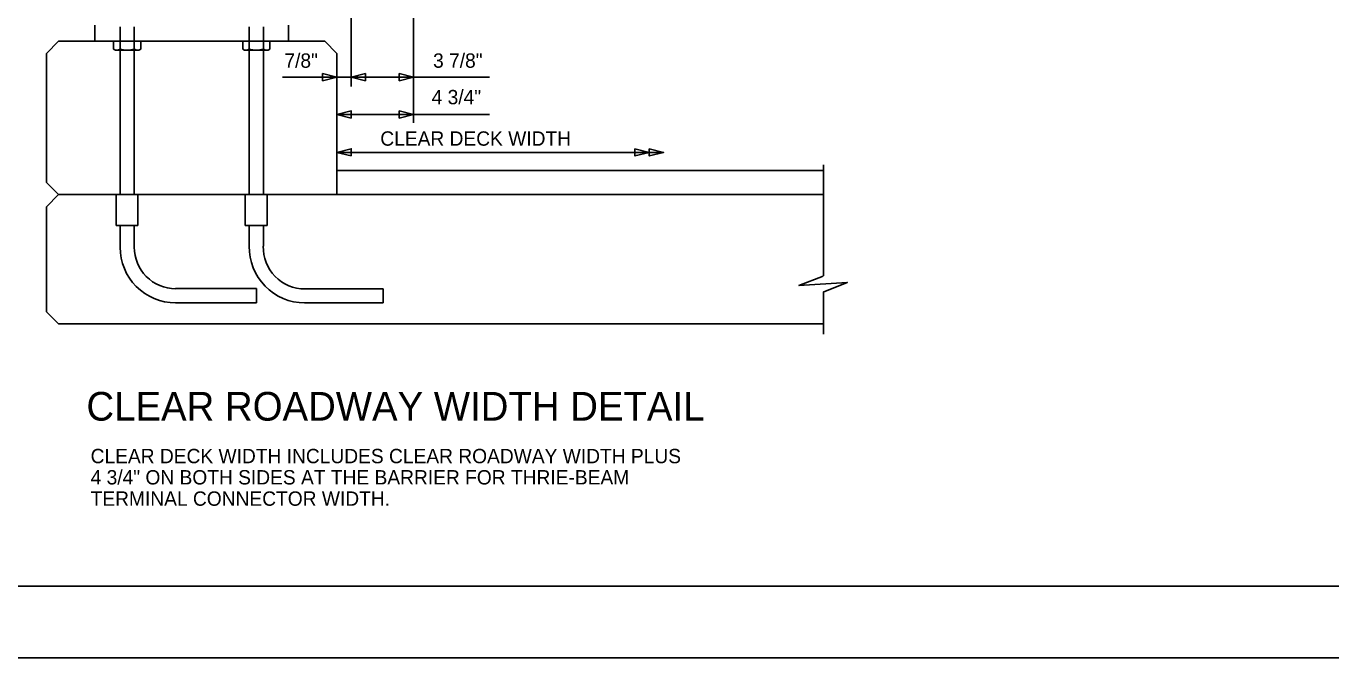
# Model space of a CAD drawing. Extents: x 641054 to 641910, y 298137 to 299325.
# Drawn here: x 641209.2 to 641482.1, y 298137.4 to 298269.4 of the extents above; entities that cross this region are included whole.
import ezdxf

# ---------------------------------------------------------------- set-up
doc = ezdxf.new("R2010")
doc.units = 0
for name, color, linetype in [('2', 7, 'Continuous'), ('3', 7, 'Continuous'), ('PLT-BNDY', 7, 'Continuous'), ('S-DETL-DIMS', 7, 'Continuous')]:
    doc.layers.add(name, color=color, linetype=linetype)

msp = doc.modelspace()

# ---------------------------------------------------------------- linework, layer by layer
at = {"layer": '2'}
for p, q in [((641290.23, 298249.21), (641290.23, 298281.94)), ((641277.16, 298273.95), (641277.16, 298256.78)), ((641223.58, 298269.62), (641223.58, 298266.25)), ((641228.86, 298269.29), (641228.86, 298234.19)), ((641231.81, 298269.29), (641231.81, 298234.19)), ((641255.86, 298269.29), (641255.86, 298234.19)), ((641258.81, 298269.29), (641258.81, 298234.19)), ((641264.08, 298269.62), (641264.08, 298266.25)), ((641213.46, 298263.72), (641215.99, 298266.25)), ((641215.99, 298266.25), (641271.68, 298266.25)), ((641227.49, 298266.25), (641227.49, 298264.62)), ((641233.18, 298266.25), (641227.49, 298266.25)), ((641228.86, 298266.25), (641228.86, 298264.62)), ((641231.81, 298266.25), (641231.81, 298264.62)), ((641233.18, 298266.25), (641233.18, 298264.62)), ((641254.49, 298266.25), (641254.49, 298264.62)), ((641260.18, 298266.25), (641254.49, 298266.25)), ((641255.86, 298266.25), (641255.86, 298264.62)), ((641258.81, 298266.25), (641258.81, 298264.62)), ((641260.18, 298266.25), (641260.18, 298264.62)), ((641274.21, 298263.72), (641271.68, 298266.25)), ((641213.46, 298263.72), (641213.46, 298236.72)), ((641227.87, 298264.4), (641227.49, 298264.62)), ((641227.87, 298264.4), (641232.79, 298264.4)), ((641232.79, 298264.4), (641233.18, 298264.62)), ((641254.87, 298264.4), (641254.49, 298264.62)), ((641254.87, 298264.4), (641259.8, 298264.4)), ((641259.8, 298264.4), (641260.18, 298264.62)), ((641274.21, 298234.19), (641274.21, 298263.72)), ((641262.84, 298258.75), (641306.13, 298258.75)), ((641274.21, 298250.95), (641306.13, 298250.95)), ((641274.21, 298243.02), (641342.54, 298243.02)), ((641375.95, 298239.25), (641274.21, 298239.25)), ((641375.95, 298240.41), (641375.95, 298219.72)), ((641215.99, 298234.19), (641213.46, 298236.72)), ((641213.46, 298231.65), (641215.99, 298234.19)), ((641375.95, 298234.19), (641215.99, 298234.19)), ((641228.03, 298234.19), (641228.03, 298227.77)), ((641232.58, 298234.19), (641228.03, 298234.19)), ((641232.58, 298234.19), (641232.58, 298227.77)), ((641255.03, 298234.19), (641255.03, 298227.77)), ((641259.58, 298234.19), (641255.03, 298234.19)), ((641259.58, 298234.19), (641259.58, 298227.77)), ((641213.46, 298231.65), (641213.46, 298209.72)), ((641232.58, 298227.77), (641228.03, 298227.77)), ((641228.86, 298227.77), (641228.86, 298223.21)), ((641231.81, 298227.77), (641231.81, 298223.2)), ((641259.58, 298227.77), (641255.03, 298227.77)), ((641255.86, 298227.77), (641255.86, 298223.42)), ((641258.81, 298227.77), (641258.81, 298223.41)), ((641257.37, 298214.55), (641240.44, 298214.55)), ((641257.37, 298214.55), (641257.37, 298211.59)), ((641283.84, 298214.49), (641267.49, 298214.49)), ((641283.84, 298214.49), (641283.84, 298211.59)), ((641375.95, 298213.81), (641375.95, 298205.03)), ((641257.37, 298211.59), (641240.44, 298211.59)), ((641283.84, 298211.59), (641267.44, 298211.59)), ((641215.99, 298207.18), (641213.46, 298209.72)), ((641375.95, 298207.18), (641215.99, 298207.18)), ((641094.49, 298152.38), (641880.49, 298152.38))]:
    msp.add_line(p, q, dxfattribs=at)
for points in [[(641271.21, 298258), (641274.21, 298258.75), (641271.21, 298259.5)], [(641280.16, 298258), (641277.16, 298258.75), (641280.16, 298259.5)], [(641287.23, 298259.5), (641290.23, 298258.75), (641287.23, 298258)], [(641277.21, 298250.2), (641274.21, 298250.95), (641277.21, 298251.7)], [(641287.23, 298251.7), (641290.23, 298250.95), (641287.23, 298250.2)], [(641277.21, 298242.27), (641274.21, 298243.02), (641277.21, 298243.77)], [(641336.53, 298243.77), (641339.53, 298243.02), (641336.53, 298242.27)], [(641339.54, 298243.77), (641342.54, 298243.02), (641339.54, 298242.27)]]:
    msp.add_lwpolyline(points, close=True, dxfattribs=at)
msp.add_lwpolyline([(641375.88, 298213.79), (641380.94, 298215.84), (641370.82, 298215.23), (641375.88, 298217.16)], dxfattribs=at)
for centre, radius, start, end in [((641228.17, 298265.57), 1.17, 269.9985, 305.701), ((641230.33, 298269.47), 5.07, 253.0634, 286.9317), ((641232.49, 298265.57), 1.17, 234.2959, 269.9983), ((641255.18, 298265.57), 1.17, 269.9985, 305.701), ((641257.33, 298269.47), 5.07, 253.0634, 286.9317), ((641259.49, 298265.57), 1.17, 234.2959, 269.9983), ((641240.44, 298223.17), 11.58, 179.7931, 270), ((641240.44, 298223.17), 8.63, 179.7931, 270), ((641267.44, 298223.17), 11.58, 178.7837, 270), ((641267.49, 298223.17), 8.69, 178.4167, 270)]:
    msp.add_arc(centre, radius, start, end, dxfattribs=at)
at = {"layer": '3'}
msp.add_line((641271.68, 298266.25), (641271.68, 298266.25), dxfattribs=at)
at = {"layer": 'PLT-BNDY'}
msp.add_lwpolyline([(641054.49, 298731.38), (641895.49, 298731.38), (641895.49, 298137.38), (641054.49, 298137.38)], close=True, dxfattribs=at)
at = {"layer": 'S-DETL-DIMS'}
msp.add_line((641375.95, 298219.72), (641375.95, 298217.19), dxfattribs=at)

# ---------------------------------------------------------------- texts
at = {"layer": '2'}
for s, height, p in [('7/8"', 3, (641263.21, 298260.71)), ('3 7/8"', 3, (641294.31, 298260.71)), ('4 3/4"', 3, (641294.01, 298253.08)), ('CLEAR DECK WIDTH', 3, (641283.27, 298244.42)), ('CLEAR ROADWAY WIDTH DETAIL', 6, (641221.8, 298186.96)), ('CLEAR DECK WIDTH INCLUDES CLEAR ROADWAY WIDTH PLUS ', 3, (641222.68, 298178.06)), ('4 3/4" ON BOTH SIDES AT THE BARRIER FOR THRIE-BEAM ', 3, (641222.68, 298173.62)), ('TERMINAL CONNECTOR WIDTH.', 3, (641222.68, 298169.17))]:
    msp.add_text(s, height=height, dxfattribs=at).set_placement(p)

doc.saveas('drawing.dxf')
